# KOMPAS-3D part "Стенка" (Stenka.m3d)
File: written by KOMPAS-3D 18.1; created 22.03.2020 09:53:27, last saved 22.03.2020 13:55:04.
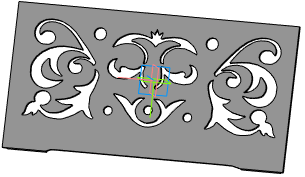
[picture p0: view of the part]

Document properties: Автор: windwican@hotmail.com; Полное имя файла: C:\Users\windw\Desktop\shkatilka1\bez petli\Stenka.m3d

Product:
- Part/product: Стенка
    Масса: 5.17309

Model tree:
1. Эскиз:1
2. Элемент выдавливания:2
     Расстояние 1 = 6
3. Эскиз:2  (with: Элемент выдавливания:2)
4. Элемент выдавливания:3
     Расстояние 1 = 10
5. Скругление:3  (with: Элемент выдавливания:3)
     Радиус = 3
6. Скругление:4  (with: Элемент выдавливания:2)
     Радиус = 1
7. Скругление:5  (with: Элемент выдавливания:2)
     Радиус = 2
